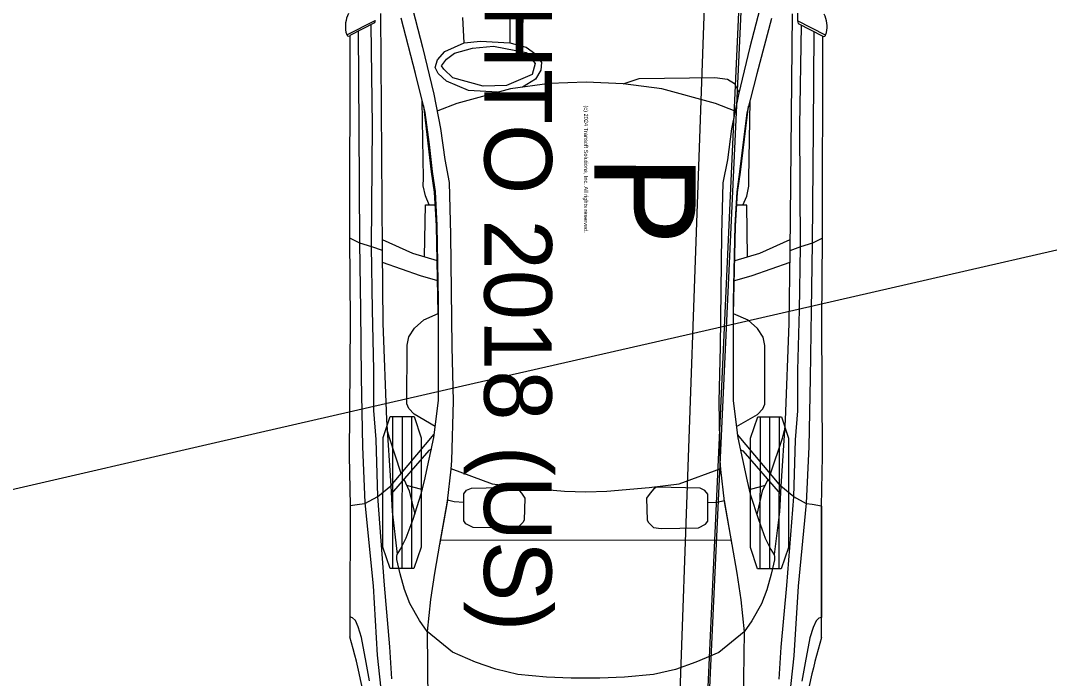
# Model space of a CAD drawing. Extents: x 17465868 to 18455672, y 7253752 to 7478845.
# Drawn here: x 18455110.2 to 18455125.43, y 7478393.99 to 7478403.72 of the extents above; entities that cross this region are included whole.
import ezdxf

# ---------------------------------------------------------------- set-up
doc = ezdxf.new("R2010")
doc.units = 0
for name, color, linetype in [('Clinton 225 CL Girders', 7, 'Continuous'), ('Clinton 225 Handrail', 7, 'Continuous'), ('Clinton 225 Metal Rail', 7, 'Continuous'), ('Dallas 126 CL Girder', 7, 'Continuous')]:
    doc.layers.add(name, color=color, linetype=linetype)

msp = doc.modelspace()

# ---------------------------------------------------------------- linework, layer by layer
at = {"layer": 'Clinton 225 CL Girders'}
for q in [(18455139.798, 7478819.136), (18455140.106, 7478819.122)]:
    msp.add_line((18455118.562, 7478354.048), q, dxfattribs=at)
at = {"layer": 'Clinton 225 Handrail'}
msp.add_line((18455118.562, 7478354.048), (18455135.011, 7478819.105), dxfattribs=at)
at = {"layer": 'Clinton 225 Metal Rail'}
for p, q in [((18455115.975, 7478404.015), (18455116.155, 7478403.331)), ((18455121.176, 7478404.01), (18455120.995, 7478403.327)), ((18455115.529, 7478403.826), (18455115.557, 7478400.323)), ((18455121.623, 7478403.82), (18455121.588, 7478400.317)), ((18455121.701, 7478403.831), (18455121.701, 7478403.719)), ((18455115.035, 7478403.511), (18455115.45, 7478403.725)), ((18455115.441, 7478403.687), (18455115.075, 7478403.499)), ((18455115.411, 7478402.169), (18455115.391, 7478403.661)), ((18455115.45, 7478403.725), (18455115.441, 7478403.687)), ((18455116.048, 7478402.941), (18455115.835, 7478403.757)), ((18455116.771, 7478403.391), (18455116.748, 7478403.768)), ((18455117.446, 7478403.793), (18455117.446, 7478403.391)), ((18455121.316, 7478403.752), (18455121.102, 7478402.936)), ((18455121.701, 7478403.719), (18455121.71, 7478403.681)), ((18455122.116, 7478403.504), (18455121.701, 7478403.719)), ((18455121.71, 7478403.681), (18455122.075, 7478403.492)), ((18455115.017, 7478403.551), (18455115.035, 7478403.511)), ((18455115.038, 7478403.505), (18455115.045, 7478403.498)), ((18455115.202, 7478403.564), (18455115.211, 7478402.137)), ((18455121.737, 7478402.163), (18455121.76, 7478403.655)), ((18455121.937, 7478402.13), (18455121.949, 7478403.557)), ((18455122.116, 7478403.504), (18455122.133, 7478403.544)), ((18455115.075, 7478403.499), (18455115.073, 7478400.51)), ((18455116.482, 7478403.266), (18455116.771, 7478403.391)), ((18455116.771, 7478403.391), (18455117.012, 7478403.416)), ((18455117.012, 7478403.416), (18455117.446, 7478403.391)), ((18455117.446, 7478403.391), (18455117.687, 7478403.328)), ((18455122.073, 7478400.503), (18455122.075, 7478403.492)), ((18455122.106, 7478403.492), (18455122.112, 7478403.498)), ((18455116.155, 7478403.331), (18455116.322, 7478402.634)), ((18455116.374, 7478403.141), (18455116.482, 7478403.266)), ((18455116.506, 7478403.153), (18455116.627, 7478403.241)), ((18455116.627, 7478403.241), (18455116.892, 7478403.316)), ((18455116.892, 7478403.316), (18455117.205, 7478403.341)), ((18455117.205, 7478403.341), (18455117.687, 7478403.252)), ((18455117.687, 7478403.328), (18455117.831, 7478403.227)), ((18455117.687, 7478403.252), (18455117.819, 7478403.089)), ((18455117.831, 7478403.227), (18455117.915, 7478403.101)), ((18455120.995, 7478403.327), (18455120.827, 7478402.63)), ((18455116.338, 7478403.028), (18455116.374, 7478403.141)), ((18455116.434, 7478403.053), (18455116.506, 7478403.153)), ((18455116.47, 7478403.002), (18455116.434, 7478403.053)), ((18455117.819, 7478403.089), (18455117.773, 7478402.922)), ((18455117.915, 7478403.101), (18455117.903, 7478402.988)), ((18455116.194, 7478402.362), (18455116.048, 7478402.941)), ((18455116.386, 7478402.94), (18455116.338, 7478403.028)), ((18455116.506, 7478402.826), (18455116.386, 7478402.94)), ((18455116.602, 7478402.877), (18455116.47, 7478403.002)), ((18455117.773, 7478402.922), (18455117.397, 7478402.763)), ((18455117.903, 7478402.988), (18455117.826, 7478402.855)), ((18455121.102, 7478402.936), (18455120.954, 7478402.358)), ((18455116.831, 7478402.688), (18455116.506, 7478402.826)), ((18455117.048, 7478402.75), (18455116.602, 7478402.877)), ((18455117.397, 7478402.763), (18455117.048, 7478402.75)), ((18455118.03, 7478402.789), (18455117.455, 7478402.714)), ((18455117.826, 7478402.855), (18455117.634, 7478402.737)), ((18455118.575, 7478402.81), (18455118.03, 7478402.789)), ((18455119.12, 7478402.788), (18455118.575, 7478402.81)), ((18455119.12, 7478402.788), (18455119.357, 7478402.867)), ((18455119.694, 7478402.712), (18455119.12, 7478402.788)), ((18455119.357, 7478402.867), (18455120.477, 7478402.878)), ((18455120.477, 7478402.878), (18455120.665, 7478402.853)), ((18455120.665, 7478402.853), (18455120.771, 7478402.792)), ((18455120.771, 7478402.792), (18455120.834, 7478402.661)), ((18455116.322, 7478402.634), (18455116.421, 7478402.125)), ((18455117.455, 7478402.714), (18455116.66, 7478402.496)), ((18455117.262, 7478402.661), (18455116.831, 7478402.688)), ((18455120.488, 7478402.493), (18455119.694, 7478402.712)), ((18455120.827, 7478402.63), (18455120.727, 7478402.121)), ((18455116.165, 7478401.392), (18455116.15, 7478402.536)), ((18455116.287, 7478401.484), (18455116.17, 7478402.459)), ((18455116.66, 7478402.496), (18455116.378, 7478402.388)), ((18455120.778, 7478402.38), (18455120.488, 7478402.493)), ((18455120.86, 7478401.479), (18455120.979, 7478402.454)), ((18455120.982, 7478401.388), (18455120.999, 7478402.532)), ((18455116.254, 7478401.888), (18455116.194, 7478402.362)), ((18455120.954, 7478402.358), (18455120.894, 7478401.884)), ((18455115.211, 7478402.137), (18455115.22, 7478400.433)), ((18455115.399, 7478400.378), (18455115.411, 7478402.169)), ((18455121.746, 7478400.372), (18455121.737, 7478402.163)), ((18455116.421, 7478402.125), (18455116.481, 7478401.665)), ((18455120.727, 7478402.121), (18455120.666, 7478401.661)), ((18455121.925, 7478400.427), (18455121.937, 7478402.13)), ((18455116.301, 7478401.49), (18455116.254, 7478401.888)), ((18455120.894, 7478401.884), (18455120.846, 7478401.486)), ((18455116.481, 7478401.665), (18455116.549, 7478401.324)), ((18455120.666, 7478401.661), (18455120.598, 7478401.32)), ((18455116.164, 7478401.275), (18455116.165, 7478401.392)), ((18455116.33, 7478401.185), (18455116.287, 7478401.484)), ((18455116.344, 7478401.191), (18455116.301, 7478401.49)), ((18455120.846, 7478401.486), (18455120.803, 7478401.187)), ((18455120.816, 7478401.18), (18455120.86, 7478401.479)), ((18455120.982, 7478401.27), (18455120.982, 7478401.388)), ((18455116.195, 7478401.128), (18455116.164, 7478401.275)), ((18455116.549, 7478401.324), (18455116.568, 7478400.559)), ((18455120.598, 7478401.32), (18455120.577, 7478400.555)), ((18455120.951, 7478401.123), (18455120.982, 7478401.27)), ((18455116.251, 7478400.995), (18455116.195, 7478401.128)), ((18455116.361, 7478400.685), (18455116.33, 7478401.185)), ((18455116.372, 7478400.692), (18455116.344, 7478401.191)), ((18455120.803, 7478401.187), (18455120.773, 7478400.688)), ((18455120.785, 7478400.681), (18455120.816, 7478401.18)), ((18455120.895, 7478400.991), (18455120.951, 7478401.123)), ((18455116.18, 7478400.229), (18455116.195, 7478400.995)), ((18455116.195, 7478400.995), (18455116.338, 7478400.995)), ((18455120.951, 7478400.99), (18455120.808, 7478400.991)), ((18455120.964, 7478400.224), (18455120.951, 7478400.99)), ((18455116.386, 7478399.387), (18455116.361, 7478400.685)), ((18455116.391, 7478399.581), (18455116.372, 7478400.692)), ((18455120.773, 7478400.688), (18455120.752, 7478399.576)), ((18455120.757, 7478399.383), (18455120.785, 7478400.681)), ((18455115.073, 7478400.51), (18455115.22, 7478400.433)), ((18455115.073, 7478400.51), (18455115.08, 7478399.271)), ((18455115.556, 7478400.482), (18455116.005, 7478400.281)), ((18455116.568, 7478400.559), (18455116.586, 7478398.897)), ((18455120.577, 7478400.555), (18455120.556, 7478398.894)), ((18455121.589, 7478400.476), (18455121.139, 7478400.276)), ((18455122.073, 7478400.503), (18455121.925, 7478400.427)), ((18455122.063, 7478399.264), (18455122.073, 7478400.503)), ((18455115.22, 7478400.433), (18455115.235, 7478399.444)), ((18455115.22, 7478400.433), (18455115.399, 7478400.378)), ((18455115.412, 7478399.444), (18455115.399, 7478400.378)), ((18455115.399, 7478400.378), (18455115.557, 7478400.323)), ((18455115.557, 7478400.323), (18455115.567, 7478399.247)), ((18455121.588, 7478400.317), (18455121.576, 7478399.242)), ((18455121.746, 7478400.372), (18455121.588, 7478400.317)), ((18455121.731, 7478399.438), (18455121.746, 7478400.372)), ((18455121.925, 7478400.427), (18455121.746, 7478400.372)), ((18455121.908, 7478399.438), (18455121.925, 7478400.427)), ((18455116.005, 7478400.281), (18455116.371, 7478400.172)), ((18455121.139, 7478400.276), (18455120.774, 7478400.167)), ((18455115.558, 7478400.148), (18455116.117, 7478399.949)), ((18455121.586, 7478400.142), (18455121.027, 7478399.945)), ((18455116.117, 7478399.949), (18455116.376, 7478399.874)), ((18455121.027, 7478399.945), (18455120.768, 7478399.87)), ((18455116.39, 7478398.582), (18455116.391, 7478399.581)), ((18455120.752, 7478399.576), (18455120.751, 7478398.577)), ((18455115.235, 7478399.444), (18455115.245, 7478398.439)), ((18455115.433, 7478398.554), (18455115.412, 7478399.444)), ((18455121.708, 7478398.548), (18455121.731, 7478399.438)), ((18455121.896, 7478398.433), (18455121.908, 7478399.438)), ((18455115.08, 7478399.271), (18455115.067, 7478397.284)), ((18455115.567, 7478399.247), (18455115.621, 7478397.815)), ((18455116.034, 7478399.172), (18455116.172, 7478399.292)), ((18455116.172, 7478399.292), (18455116.386, 7478399.387)), ((18455120.971, 7478399.288), (18455120.757, 7478399.383)), ((18455121.109, 7478399.167), (18455120.971, 7478399.288)), ((18455121.576, 7478399.242), (18455121.519, 7478397.809)), ((18455122.072, 7478397.277), (18455122.063, 7478399.264)), ((18455115.949, 7478399.043), (18455116.034, 7478399.172)), ((18455121.193, 7478399.038), (18455121.109, 7478399.167)), ((18455115.927, 7478398.919), (18455115.949, 7478399.043)), ((18455121.216, 7478398.914), (18455121.193, 7478399.038)), ((18455115.92, 7478398.053), (18455115.927, 7478398.919)), ((18455116.586, 7478398.897), (18455116.604, 7478398.092)), ((18455120.556, 7478398.894), (18455120.536, 7478398.088)), ((18455121.22, 7478398.048), (18455121.216, 7478398.914)), ((18455115.433, 7478397.954), (18455115.433, 7478398.554)), ((18455116.389, 7478398.102), (18455116.39, 7478398.582)), ((18455120.751, 7478398.577), (18455120.751, 7478398.098)), ((18455121.708, 7478397.948), (18455121.708, 7478398.548)), ((18455115.245, 7478398.439), (18455115.266, 7478397.422)), ((18455121.873, 7478397.416), (18455121.896, 7478398.433)), ((18455115.951, 7478397.98), (18455115.92, 7478398.053)), ((18455116.321, 7478397.552), (18455116.389, 7478398.102)), ((18455116.604, 7478398.092), (18455116.584, 7478397.215)), ((18455120.536, 7478398.088), (18455120.555, 7478397.212)), ((18455120.751, 7478398.098), (18455120.819, 7478397.548)), ((18455121.189, 7478397.976), (18455121.22, 7478398.048)), ((18455115.465, 7478397.526), (18455115.433, 7478397.954)), ((18455116.028, 7478397.9), (18455115.951, 7478397.98)), ((18455116.341, 7478397.718), (18455116.028, 7478397.9)), ((18455120.798, 7478397.714), (18455121.112, 7478397.896)), ((18455121.112, 7478397.896), (18455121.189, 7478397.976)), ((18455121.674, 7478397.52), (18455121.708, 7478397.948)), ((18455115.621, 7478397.815), (18455115.683, 7478396.838)), ((18455115.711, 7478397.865), (18455115.709, 7478395.615)), ((18455115.851, 7478397.865), (18455115.849, 7478395.615)), ((18455115.992, 7478397.865), (18455115.99, 7478395.615)), ((18455121.148, 7478397.86), (18455121.146, 7478395.61)), ((18455121.289, 7478397.86), (18455121.287, 7478395.61)), ((18455121.429, 7478397.86), (18455121.427, 7478395.61)), ((18455121.519, 7478397.809), (18455121.455, 7478396.833)), ((18455115.662, 7478397.546), (18455115.63, 7478397.665)), ((18455115.683, 7478396.838), (18455116.327, 7478397.604)), ((18455121.455, 7478396.833), (18455120.812, 7478397.6)), ((18455121.478, 7478397.541), (18455121.509, 7478397.66)), ((18455115.266, 7478397.422), (18455115.301, 7478396.587)), ((18455115.492, 7478396.681), (18455115.465, 7478397.526)), ((18455115.839, 7478397.023), (18455115.662, 7478397.546)), ((18455116.183, 7478396.91), (18455116.321, 7478397.552)), ((18455120.819, 7478397.548), (18455120.955, 7478396.905)), ((18455121.3, 7478397.018), (18455121.478, 7478397.541)), ((18455121.646, 7478396.675), (18455121.674, 7478397.52)), ((18455121.837, 7478396.581), (18455121.873, 7478397.416)), ((18455115.067, 7478397.284), (18455115.08, 7478396.545)), ((18455116.247, 7478397.362), (18455115.69, 7478396.72)), ((18455116.284, 7478397.382), (18455116.247, 7478397.362)), ((18455120.855, 7478397.377), (18455120.892, 7478397.358)), ((18455120.892, 7478397.358), (18455121.448, 7478396.714)), ((18455122.058, 7478396.538), (18455122.072, 7478397.277)), ((18455116.584, 7478397.215), (18455116.574, 7478397.083)), ((18455120.555, 7478397.212), (18455120.564, 7478397.079)), ((18455116.574, 7478397.083), (18455116.519, 7478396.612)), ((18455116.572, 7478397.097), (18455117.185, 7478396.868)), ((18455119.953, 7478396.866), (18455120.567, 7478397.093)), ((18455120.564, 7478397.079), (18455120.619, 7478396.608)), ((18455115.492, 7478396.681), (18455115.683, 7478396.838)), ((18455115.683, 7478396.838), (18455115.703, 7478396.46)), ((18455115.878, 7478396.936), (18455115.957, 7478396.762)), ((18455115.917, 7478396.849), (18455116.151, 7478396.783)), ((18455116.135, 7478396.719), (18455116.183, 7478396.91)), ((18455116.805, 7478396.773), (18455116.878, 7478396.806)), ((18455116.878, 7478396.806), (18455117.523, 7478396.818)), ((18455117.185, 7478396.868), (18455117.633, 7478396.814)), ((18455117.523, 7478396.818), (18455117.564, 7478396.796)), ((18455117.633, 7478396.814), (18455118.256, 7478396.759)), ((18455118.881, 7478396.758), (18455119.505, 7478396.812)), ((18455119.505, 7478396.812), (18455119.953, 7478396.866)), ((18455119.615, 7478396.816), (18455119.574, 7478396.794)), ((18455120.26, 7478396.803), (18455119.615, 7478396.816)), ((18455120.955, 7478396.905), (18455121.003, 7478396.714)), ((18455121.221, 7478396.844), (18455120.987, 7478396.779)), ((18455121.261, 7478396.931), (18455121.181, 7478396.757)), ((18455121.455, 7478396.833), (18455121.434, 7478396.455)), ((18455121.646, 7478396.675), (18455121.455, 7478396.833)), ((18455115.301, 7478396.576), (18455115.492, 7478396.681)), ((18455115.592, 7478395.369), (18455115.492, 7478396.681)), ((18455115.957, 7478396.762), (18455116.039, 7478396.419)), ((18455116.014, 7478396.343), (18455116.135, 7478396.719)), ((18455116.764, 7478396.719), (18455116.805, 7478396.773)), ((18455116.764, 7478396.318), (18455116.764, 7478396.719)), ((18455117.564, 7478396.796), (18455117.616, 7478396.731)), ((18455117.616, 7478396.731), (18455117.668, 7478396.656)), ((18455117.668, 7478396.656), (18455117.659, 7478396.33)), ((18455118.256, 7478396.759), (18455118.569, 7478396.748)), ((18455118.569, 7478396.748), (18455118.881, 7478396.758)), ((18455119.522, 7478396.73), (18455119.469, 7478396.654)), ((18455119.469, 7478396.654), (18455119.479, 7478396.328)), ((18455119.574, 7478396.794), (18455119.522, 7478396.73)), ((18455120.333, 7478396.77), (18455120.26, 7478396.803)), ((18455120.374, 7478396.715), (18455120.333, 7478396.77)), ((18455120.373, 7478396.314), (18455120.374, 7478396.715)), ((18455121.003, 7478396.714), (18455121.123, 7478396.338)), ((18455121.181, 7478396.757), (18455121.099, 7478396.414)), ((18455121.544, 7478395.364), (18455121.646, 7478396.675)), ((18455121.837, 7478396.57), (18455121.646, 7478396.675)), ((18455115.08, 7478396.545), (18455115.078, 7478394.898)), ((18455115.08, 7478396.545), (18455115.221, 7478396.566)), ((18455115.221, 7478396.566), (18455115.301, 7478396.576)), ((18455115.301, 7478396.587), (18455115.421, 7478395.359)), ((18455116.519, 7478396.612), (18455116.404, 7478395.973)), ((18455116.522, 7478396.626), (18455116.405, 7478395.967)), ((18455116.623, 7478396.602), (18455116.522, 7478396.626)), ((18455116.764, 7478396.594), (18455116.623, 7478396.602)), ((18455120.374, 7478396.591), (18455120.515, 7478396.598)), ((18455120.515, 7478396.598), (18455120.616, 7478396.622)), ((18455120.616, 7478396.622), (18455120.731, 7478395.963)), ((18455120.619, 7478396.608), (18455120.732, 7478395.969)), ((18455121.715, 7478395.353), (18455121.837, 7478396.581)), ((18455121.917, 7478396.56), (18455121.837, 7478396.57)), ((18455122.058, 7478396.538), (18455121.917, 7478396.56)), ((18455122.058, 7478396.538), (18455122.056, 7478394.891)), ((18455122.056, 7478394.891), (18455122.058, 7478396.538)), ((18455115.703, 7478396.46), (18455115.78, 7478395.825)), ((18455121.434, 7478396.455), (18455121.356, 7478395.82)), ((18455115.912, 7478396.068), (18455116.014, 7478396.343)), ((18455116.796, 7478396.274), (18455116.764, 7478396.318)), ((18455116.9, 7478396.22), (18455116.796, 7478396.274)), ((18455117.451, 7478396.21), (18455116.9, 7478396.22)), ((18455117.565, 7478396.222), (18455117.451, 7478396.21)), ((18455117.638, 7478396.298), (18455117.565, 7478396.222)), ((18455117.659, 7478396.33), (18455117.638, 7478396.298)), ((18455119.479, 7478396.328), (18455119.499, 7478396.296)), ((18455119.499, 7478396.296), (18455119.572, 7478396.22)), ((18455119.572, 7478396.22), (18455119.686, 7478396.208)), ((18455119.686, 7478396.208), (18455120.237, 7478396.217)), ((18455120.237, 7478396.217), (18455120.341, 7478396.271)), ((18455120.341, 7478396.271), (18455120.373, 7478396.314)), ((18455121.123, 7478396.338), (18455121.225, 7478396.063)), ((18455115.828, 7478395.899), (18455115.912, 7478396.068)), ((18455121.225, 7478396.063), (18455121.308, 7478395.894)), ((18455115.78, 7478395.824), (18455115.828, 7478395.899)), ((18455116.404, 7478395.973), (18455116.332, 7478395.548)), ((18455120.722, 7478396.029), (18455116.415, 7478396.033)), ((18455120.732, 7478395.969), (18455120.804, 7478395.544)), ((18455121.308, 7478395.894), (18455121.356, 7478395.819)), ((18455115.774, 7478395.799), (18455115.78, 7478395.824)), ((18455115.774, 7478395.749), (18455115.774, 7478395.799)), ((18455115.821, 7478395.536), (18455115.774, 7478395.749)), ((18455121.362, 7478395.743), (18455121.314, 7478395.531)), ((18455121.356, 7478395.819), (18455121.362, 7478395.793)), ((18455121.362, 7478395.793), (18455121.362, 7478395.743)), ((18455115.887, 7478395.304), (18455115.821, 7478395.536)), ((18455116.332, 7478395.548), (18455116.271, 7478395.154)), ((18455120.804, 7478395.544), (18455120.864, 7478395.149)), ((18455121.314, 7478395.531), (18455121.248, 7478395.299)), ((18455115.421, 7478395.359), (18455115.48, 7478394.331)), ((18455115.671, 7478394.456), (18455115.592, 7478395.369)), ((18455115.965, 7478395.097), (18455115.887, 7478395.304)), ((18455121.248, 7478395.299), (18455121.17, 7478395.093)), ((18455121.462, 7478394.451), (18455121.544, 7478395.364)), ((18455121.653, 7478394.325), (18455121.715, 7478395.353)), ((18455116.271, 7478395.154), (18455116.223, 7478394.684)), ((18455120.864, 7478395.149), (18455120.911, 7478394.68)), ((18455116.109, 7478394.847), (18455115.965, 7478395.097)), ((18455121.17, 7478395.093), (18455121.025, 7478394.842)), ((18455115.118, 7478394.887), (18455115.078, 7478394.898)), ((18455115.078, 7478394.898), (18455115.078, 7478394.603)), ((18455115.159, 7478394.845), (18455115.118, 7478394.887)), ((18455115.199, 7478394.751), (18455115.159, 7478394.845)), ((18455116.223, 7478394.684), (18455116.109, 7478394.847)), ((18455121.025, 7478394.842), (18455120.911, 7478394.68)), ((18455121.976, 7478394.839), (18455121.935, 7478394.744)), ((18455122.016, 7478394.881), (18455121.976, 7478394.839)), ((18455122.056, 7478394.891), (18455122.016, 7478394.881)), ((18455122.056, 7478394.596), (18455122.056, 7478394.891)), ((18455115.249, 7478394.593), (18455115.199, 7478394.751)), ((18455116.223, 7478394.684), (18455116.243, 7478392.607)), ((18455116.596, 7478394.375), (18455116.223, 7478394.684)), ((18455120.911, 7478394.68), (18455120.537, 7478394.371)), ((18455120.911, 7478394.68), (18455120.887, 7478392.603)), ((18455121.935, 7478394.744), (18455121.885, 7478394.587)), ((18455115.319, 7478394.226), (18455115.249, 7478394.593)), ((18455121.885, 7478394.587), (18455121.814, 7478394.22)), ((18455115.701, 7478393.984), (18455115.671, 7478394.456)), ((18455116.935, 7478394.231), (18455116.596, 7478394.375)), ((18455120.537, 7478394.371), (18455120.198, 7478394.228)), ((18455121.432, 7478393.979), (18455121.462, 7478394.451)), ((18455115.369, 7478393.953), (18455115.319, 7478394.226)), ((18455115.48, 7478394.331), (18455115.55, 7478393.69)), ((18455117.237, 7478394.126), (18455116.935, 7478394.231)), ((18455120.198, 7478394.228), (18455119.896, 7478394.123)), ((18455121.582, 7478393.685), (18455121.653, 7478394.325)), ((18455121.814, 7478394.22), (18455121.764, 7478393.947)), ((18455117.563, 7478394.047), (18455117.237, 7478394.126)), ((18455119.896, 7478394.123), (18455119.57, 7478394.045)), ((18455117.99, 7478394.007), (18455117.563, 7478394.047)), ((18455118.354, 7478393.994), (18455117.99, 7478394.007)), ((18455118.566, 7478393.993), (18455118.354, 7478393.994)), ((18455118.779, 7478393.993), (18455118.566, 7478393.993)), ((18455119.143, 7478394.006), (18455118.779, 7478393.993)), ((18455119.57, 7478394.045), (18455119.143, 7478394.006))]:
    msp.add_line(p, q, dxfattribs=at)
for points in [[(18455115.676, 7478397.865), (18455116.027, 7478397.865), (18455116.132, 7478397.55), (18455116.131, 7478395.93), (18455116.025, 7478395.615), (18455115.674, 7478395.615), (18455115.568, 7478395.931), (18455115.57, 7478397.551)], [(18455121.113, 7478397.86), (18455121.464, 7478397.86), (18455121.57, 7478397.545), (18455121.568, 7478395.925), (18455121.462, 7478395.61), (18455121.111, 7478395.61), (18455121.006, 7478395.925), (18455121.007, 7478397.545)]]:
    msp.add_lwpolyline(points, close=True, dxfattribs=at)
for centre, radius, start, end in [((18455115.456, 7478403.631), 0.445, 154.2176, 190.3459), ((18455121.695, 7478403.625), 0.445, 349.5453, 25.6736), ((18455115.052, 7478403.518), 0.019, 202.7707, 223.8405), ((18455115.06, 7478403.516), 0.0236, 230.107, 311.6042), ((18455078.494, 7478368.538), 50.578, 43.72593027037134, 43.72593071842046), ((18455122.091, 7478403.51), 0.0236, 228.287, 309.7842), ((18455122.099, 7478403.511), 0.0183, 315.6007, 337.5705), ((18455106.886, 7478392.196), 8.538, 6.4143, 16.3778), ((18455130.243, 7478392.173), 8.538, 163.5134, 173.477)]:
    msp.add_arc(centre, radius, start, end, dxfattribs=at)
at = {"layer": 'Dallas 126 CL Girder'}
for radius in [15064.793, 15052.793, 15040.793, 15028.793, 15018.793, 14988.793, 14978.793, 14966.793, 14954.793, 14942.793]:
    msp.add_arc((18458471.778, 7463759.052), radius, 101.0668789, 104.665109, dxfattribs=at)

# ---------------------------------------------------------------- texts
at = {"layer": 'Clinton 225 Metal Rail'}
for s, height, p in [('AASHTO 2018 (US)', 1, (18455117.073, 7478406.65)), ('(c) 2024 Transoft Solutions, Inc. All rights reserved.', 0.06, (18455118.544, 7478402.466)), ('P', 1.5, (18455118.694, 7478401.738))]:
    msp.add_text(s, height=height, rotation=269.9456, dxfattribs=at).set_placement(p)

doc.saveas('drawing.dxf')
